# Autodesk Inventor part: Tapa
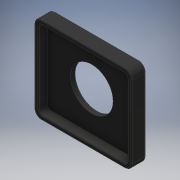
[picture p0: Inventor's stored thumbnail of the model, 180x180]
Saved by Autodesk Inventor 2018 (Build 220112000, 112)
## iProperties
Created: 2022-01
Part Number: Tapa
Material: Caucho, Silicona
Document SubType Name: Modeling
Designer: Asus
Density: 1.25 g/cm^3
Appearance: Goma - Negro
Author: Asus
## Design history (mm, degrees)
sketch "Boceto1"
  geometry: L1 (125, 110)-(-125, 110); L2 (-125, 110)-(-125, -110); L3 (-125, -110)-(125, -110); L4 (125, -110)-(125, 110); L5 (125, 110)-(-125, -110); L6 (-125, 110)-(125, -110); L7 (137.5, 122.5)-(-137.5, 122.5); L8 (-137.5, 122.5)-(-137.5, -122.5); L9 (-137.5, -122.5)-(137.5, -122.5); L10 (137.5, -122.5)-(137.5, 122.5); L11 (137.5, 122.5)-(-137.5, -122.5); L12 (-137.5, 122.5)-(137.5, -122.5); 1 further point
  constraints: 24 end point, 4 midpoint, 4 parallel, 2 horizontal, 2 perpendicular
  dimensions: "d0" = 250 distance of L3.end L2.end; "d1" = 220 distance of L2.end L1.end; "d2" = 275 distance of L9.end L8.end; "d3" = 245 distance of L8.end L7.end
extrude "Extrusión1" new body sketch "Boceto1" distance "d4" = 25; taper "d5" = 0 deg
extrude "Extrusión2" join sketch "Boceto1" distance "d6" = 15; taper "d7" = 0 deg
sketch "Boceto2"
  geometry: C1 r 60 at (0, 0); 1 further point
  constraints: 1 centre point, 1 coincident
  dimensions: "d8" = 120 diameter of C1
fillet "Empalme1" dims "d9" = 20
fillet "Empalme2" dims "d10" = 10
extrude "Extrusión3" cut sketch "Boceto2" distance "d11" = 25; taper "d12" = 0 deg
fillet "Empalme3" dims "d13" = 2.5
node "Sólido1"
